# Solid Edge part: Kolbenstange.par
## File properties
Username: bmolnar
Dokumentum tartalom típus: 0
Author: bmolnar
Last saved by: bmolnar
Revision: 92
Sűrűség: 0,000 kg/m^3
Pontosság: 0,990
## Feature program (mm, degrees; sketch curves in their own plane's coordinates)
base feature "unnamed BaseFeature 1"
sketch for "unnamed Protrusion 1" plane through (23.5, 0, 0) normal (1, 0, 0) x-axis (0, -1, 0)
  circle centre (0, 0) radius 12.5
extrude "unnamed Protrusion 1" add finite 7 along +normal
thread "Menet_1"  ThreadDepth = 15 mm
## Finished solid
Body 1: solid body, 15 faces, 21 edges, 8 vertices.
  Faces by surface: plane 8, cylinder 4, cone 2, torus 1
  Edges by curve: circle 11, line 6, ellipse 2, intersection 2
Bounding box of the edges (mm; curved faces can reach further): 225.500 x 25.000 x 25.000, from (-195, -12.5, -12.5) to (30.5, 12.5, 12.5).
Cylindrical faces by radius (mm): R2.4585 x2, R5 x1, R12.5 x1
Conical faces (half-angle, radius in mm at the cone's reference point): 45 deg R2.8085 x1, 59 deg R1.2292 x1
Toroidal faces (ring radius, tube radius in mm): R3.8 r1.2 x1
Planar faces by outward normal: +x 1, +z 1, -x 3, -z 1, oblique 2
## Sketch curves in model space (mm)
circle centre (23.5, 0, 0) radius 12.5
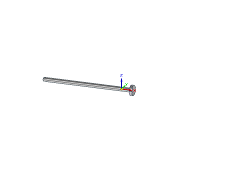
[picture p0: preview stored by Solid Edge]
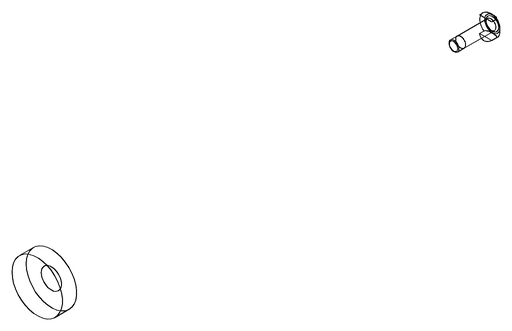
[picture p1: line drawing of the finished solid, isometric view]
